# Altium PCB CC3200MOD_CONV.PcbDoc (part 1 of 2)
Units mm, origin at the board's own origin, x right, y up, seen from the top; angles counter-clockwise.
Board outline 40.99 x 49.89 mm, 2 copper layers (Top Layer, Bottom Layer), stack 1.071 mm thick; 81 components, 78 nets, 312 pads, 246 vias.
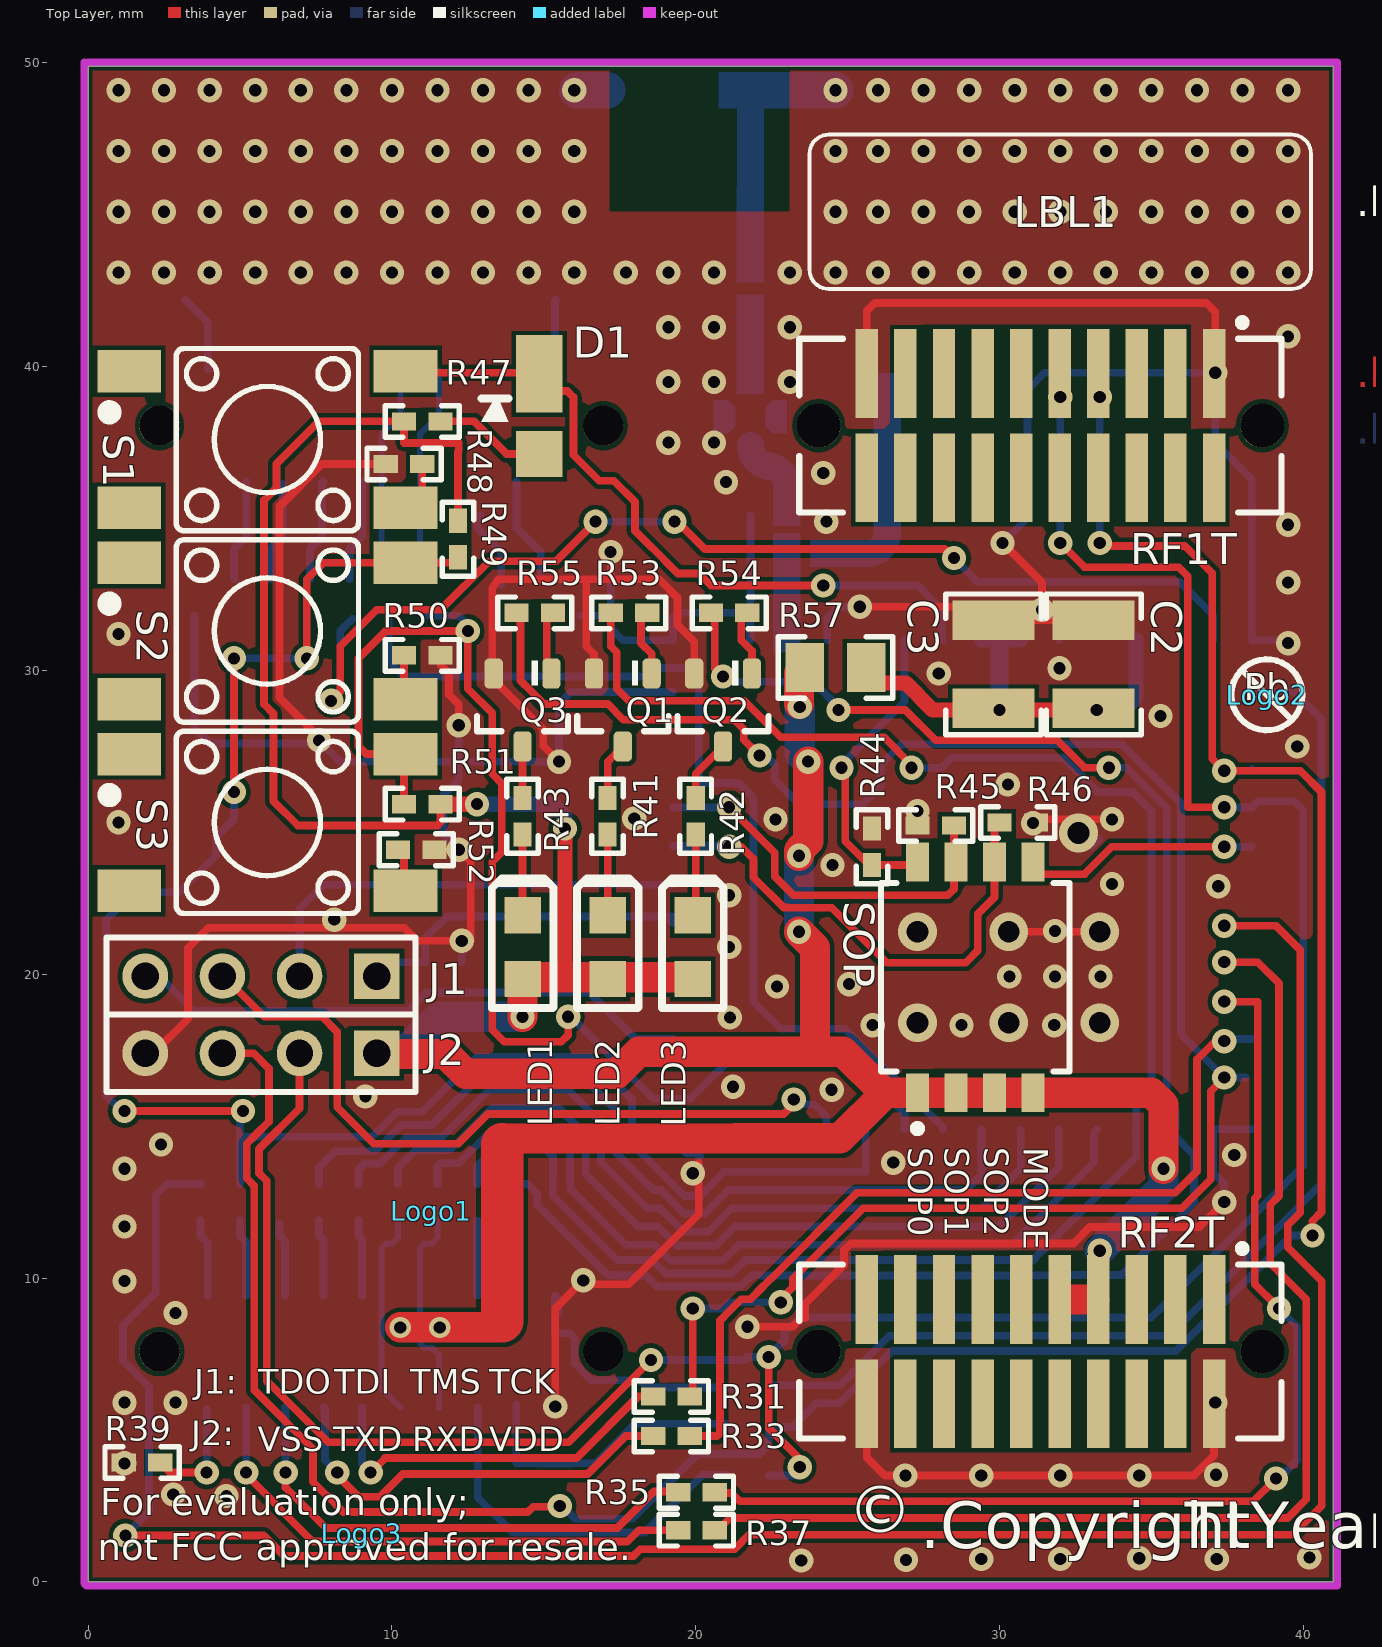
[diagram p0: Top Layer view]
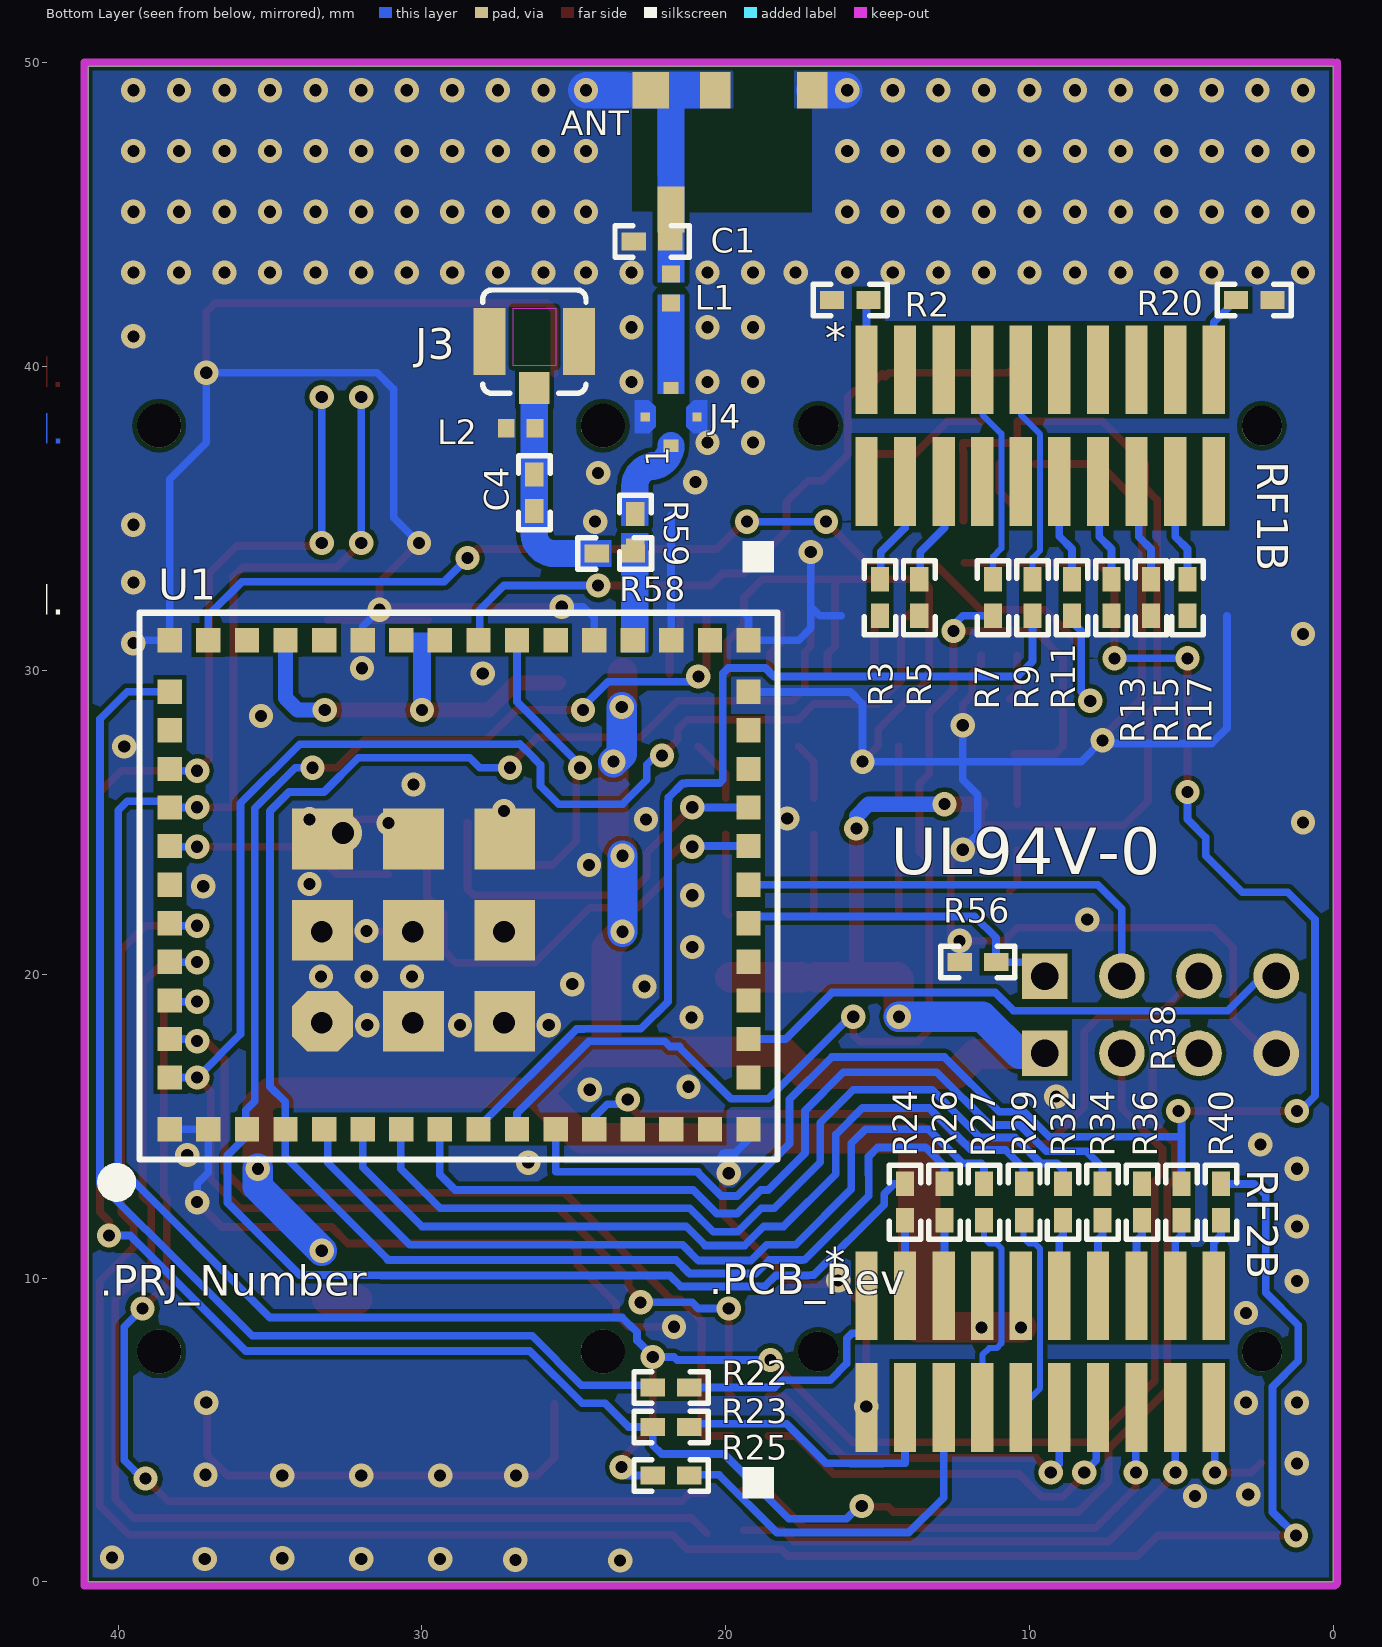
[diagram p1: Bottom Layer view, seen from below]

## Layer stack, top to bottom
Top Layer: signal copper 0.0356
Dielectric: core 1, FR-4, Dk 4.8
Bottom Layer: signal copper 0.0356

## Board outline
0,0 0,49.894 40.988,49.894 40.988,0

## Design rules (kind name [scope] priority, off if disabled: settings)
AcuteAngle [All] p1: minimum=4.50000000000000E+0001 checktracksonly=FALSE
AssemblyTestPointUsage [All] p1: valid=2
Clearance Clearance_BoardEdge_MountingHoles [OnCopper and InComponentClass('Mounting Holes') vs IsKeepOut] p1: gap=1.016
Clearance Clearance_BoardEdge_Poly [OnCopper and InPoly vs IsKeepOut] p2: gap=0.152
Clearance Clearance_BoardEdge [OnCopper and Not InComponentClass('Logo') and not InComponentClass('FiducialMark') and not InRegion(1000,500,4000,800) and Not IsKeepout vs IsKeepOut] p3: gap=0.152
Clearance Clearance_Poly [InPolygon] p4: gap=0.152
Clearance [All] p5: gap=0.152
ComponentClearance ComponentClearance_Shunt [InComponentClass('Header') vs InComponentClass('Shunt')] p1: gap=0.127 collisioncheckmode=3 verticalgap=0 showdistances=FALSE
ComponentClearance ComponentClearance_MountingHoles_FiducialMarks [InComponentClass('Mounting Holes') vs InComponentClass('FiducialMark')] p2 off: gap=0.127 collisioncheckmode=3 verticalgap=0.254 showdistances=FALSE
ComponentClearance ComponentClearance_Logo [InComponentClass('Logo')] p3: gap=1.27 collisioncheckmode=3 verticalgap=0.254 showdistances=FALSE
ComponentClearance ComponentClearance_ScrewToNut [(HasFootprint('NY PMS 440 0025 PH')) vs (HasFootprint('Keystone_1902C'))] p4: gap=0.127 collisioncheckmode=3 verticalgap=0.254 showdistances=FALSE
ComponentClearance ComponentClearance_MountingHoles [InComponentClass('Mounting Holes')] p5: gap=6.35 collisioncheckmode=3 verticalgap=2540 showdistances=FALSE
ComponentClearance ComponentClearance_SmallPassives [HasFootprint('0201*') or HasFootprint('0402*') or HasFootprint('0508') or HasFootprint('0603*') or HasFootprint('0612') or HasFootprint('0805*') or HasFootprint('0815*') or HasFootprint('0830*') or HasFootprint('1206*') or HasFootprint('1210*') or HasFootprint('1808*') or HasFootprint('1812*') or HasFootprint('1825*') or HasFootprint('2010*') or HasFootprint('2220*') or HasFootprint('2225*') or HasFootprint('2512*') or HasFootprint('2728*') or HasFootprint('3518*') vs HasFootprint('0201*') or HasFootprint('0402*') or HasFootprint('0508') or HasFootprint('0603*') or HasFootprint('0612') or HasFootprint('0805*') or HasFootprint('0815*') or HasFootprint('0830*') or HasFootprint('1206*') or HasFootprint('1210*') or HasFootprint('1808*') or HasFootprint('1812*') or HasFootprint('1825*') or HasFootprint('2010*') or HasFootprint('2220*') or HasFootprint('2225*') or HasFootprint('2512*') or HasFootprint('2728*') or HasFootprint('3518*')] p6: gap=0.508 collisioncheckmode=3 verticalgap=0.254 showdistances=FALSE
ComponentClearance ComponentClearance_THtoSMT [IsThruComponent vs IsSMTComponent] p7: gap=0.127 collisioncheckmode=3 verticalgap=0.762 showdistances=FALSE
ComponentClearance ComponentClearance_THtoTH [IsThruComponent vs IsThruComponent] p8: gap=0.127 collisioncheckmode=3 verticalgap=0.762 showdistances=FALSE
ComponentClearance [All] p9: gap=0.127 collisioncheckmode=3 verticalgap=0.254 showdistances=FALSE
DiffPairsRouting [All] p1: maxlimit=2.54 minlimit=0.254 mostfreqgap=0.254 maxuncoupledlength=25.4
FabricationTestPointUsage TestPointUsage [All] p1: valid=2 allowmultiple=FALSE
FabricationTestpoint Testpoint [All] p1: side=3 testpointundercomponent=TRUE minsize=1.016 maxsize=2.54 preferedsize=1.524 minholesize=0 maxholesize=1.016 preferedholesize=0.813 testpointgrid=0.025 allowsidetop=TRUE allowsidebottom=TRUE usegrid=TRUE gridtolerance=0
FanoutControl Fanout_LCC [IsLCC] p1: bgadir=Out bgaviamode=Centered fanoutstyle=Auto fanoutdirection=Alternating viagrid=0.025 // Fanout_LCC (Default Rule)
FanoutControl Fanout_BGA [IsBGA] p2: bgadir=Out bgaviamode=Centered fanoutstyle=Auto fanoutdirection=Alternating viagrid=0.025 // Fanout_BGA (Default Rule)
FanoutControl Fanout_Default [All] p4: bgadir=Out bgaviamode=Centered fanoutstyle=Auto fanoutdirection=Alternating viagrid=0.025 // Fanout_Default (Default Rule)
FanoutControl Fanout_Small [(CompPinCount < 5)] p5: bgadir=Out bgaviamode=Centered fanoutstyle=Auto fanoutdirection=OutThenIn viagrid=0.025 // Fanout_Small (Default Rule)
HoleSize [All] p1: absolutevalues=TRUE maxlimit=6.375 minlimit=0.203 maxpercent=80.000 minpercent=20.000
MinimumAnnularRing MinimumAnnularRing_ThermalPadVias [IsVia and InAnyComponent] p1: minimumring=0.15
MinimumAnnularRing [All] p2: minimumring=0.2
MinimumSolderMaskSliver MinimumSolderMaskSliver_Logo [InComponentClass('Logo') vs InComponentClass('Logo')] p1: minsoldermaskwidth=0.018
MinimumSolderMaskSliver [All] p2: minsoldermaskwidth=0.1
PlaneClearance [All] p1: clearance=0.152
PlaneConnect [All] p1: planeconnectstyle=Direct reliefexpansion=0.254 reliefentries=4 reliefconductorwidth=0.254 reliefairgap=0.254
PolygonConnect [All] p1: connectstyle=Direct reliefconductorwidth=0.254 reliefentries=4 polygonreliefangle="90 Angle" airgapwidth=0.254
RoutingVias ThermalPadVias [IsVia and InAnyComponent] p1: holewidth=0.2 width=0.5 viastyle="Through Hole" minholewidth=0.2 minwidth=0.5 maxholewidth=0.33 maxwidth=0.6
RoutingVias [All] p2: holewidth=0.406 width=0.864 viastyle="Through Hole" minholewidth=0.2 minwidth=0.66 maxholewidth=1.016 maxwidth=1.651
SMDToCorner [All] p1: distance=30000
SilkToSilkClearance SilkToSilkClearance_Pb-FreeLogo [(HasFootprint('Pb-Free_Overlay_Medium') OR HasFootprint('Pb-Free_Overlay_Small')) vs (HasFootprint('Pb-Free_Overlay_Medium') OR HasFootprint('Pb-Free_Overlay_Small'))] p1: silktosilkclearance=0
SilkToSilkClearance [All] p2: silktosilkclearance=0
SilkscreenOverComponentPads [IsPad] p1: minsilkscreentomaskgap=0.127
SolderMaskExpansion [All] p1: expansion=0.05
Width [All] p1: maxlimit=2.54 minlimit=0.127 preferedwidth=0.254 checkconnectedcopper=TRUE
13 further rules are at their usual default settings.

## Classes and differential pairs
component class Logo: Logo1
component class Hardware_CC3200MOD_CONV: LBL1 Logo2 Logo3 ZZ1 ZZ2 ZZ3 ZZ4
component class AssemblyNote: ZZ1 ZZ2 ZZ3 ZZ4
component class Label: LBL1
component class CC3200MOD_CONV: 0.8 ANT C1 C2 C3 C4 D1 J1 J2 J3 J4 L1 L2 LED1 LED2 LED3 Logo1 Q1 Q2 Q3 R2 R3 R5 R7 R9 R11 R13 R15 R17 R20 R22 R23 R24 R25 R26 R27 R29 R31 R32 R33 R34 R35 R36 R37 R38 R39 R40 R41 R42 R43 R44 R45 R46 R47 R48 R49 R50 R51 R52 R53 R54 R55 R56 R57 R58 R59 RF1B RF1T RF2B RF2T S1 S2 S3 SOP U1

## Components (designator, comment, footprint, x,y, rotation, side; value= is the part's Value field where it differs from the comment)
ANT "AH316M245001-T" AH316M 18.75,49.1 r180 bottom
C1 "GRM1555C1H1R0BA01D" 0402 22.425,44.125 r180 bottom
C2 "GRM32ER60J107ME20L" 1210 33.1,30.2 r90 top
C3 "GRM32ER60J107ME20L" 1210 29.8,30.2 r90 top
C4 "GRM1555C1H100JA01D" 0402 26.3,35.85 r90 bottom
D1 "D_SCHOT_DFLS160" POWERDI_123 14.85,38.7 r270 top
J1 "JTAG" HDR1X4 9.5,19.94 r180 top
J2 "Spare UART for serial flash programming" HDR1X4 9.5,17.4 r180 top
J3 "U.FL-R-SMT-1" CONN_UFL-R-SMT-1 26.3,40.825 r90 bottom
J4 "CONN_MICROWAVE-MM8030-2600" CONN_MICRO-MM8030-2600 21.8,38.35 r0 bottom
L1 "LQP15MN3N6B02D" LQP_0402 21.8,42.575 r90 bottom
L2 "DNP" LQP_0402 26.75,37.975 r180 bottom
LBL1 "Size: 0.65\" x 0.20 \"" Label_650x200 32,45.1 r0 top
LED1 "Red" 0805-LED 14.3,20.9 r90 top
LED2 "Green" 0805-LED 17.1,20.9 r90 top
LED3 "Blue" 0805-LED 19.9,20.9 r90 top
Logo1 "Texas Instruments" TI_Stacked_SolderMask_Small 11.3,12.2 r0 top
Logo2 "Pb-Free Symbol" Pb-Free_Overlay_Small 38.8,29.2 r0 top
Logo3 "FCC disclaimer" FCC_disclaimer_stacked 9,1.6 r0 top
Q1 "BSS138" SOT-23 17.6,28.7 r270 top
Q2 "BSS138" SOT-23 20.9,28.7 r270 top
Q3 "BSS138" SOT-23 14.3,28.7 r270 top
R2 "CRCW04020000Z0ED" 0402 15.9,42.2 r180 bottom
R3 "CRCW04020000Z0ED (Phantom)" 0402 14.918,32.4 r90 bottom
R5 "CRCW04020000Z0ED (Phantom)" 0402 13.627,32.4 r90 bottom
R7 "CRCW04020000Z0ED" 0402 11.2,32.4 r90 bottom
R9 "CRCW04020000Z0ED" 0402 9.9,32.4 r90 bottom
R11 "CRCW04020000Z0ED (Phantom)" 0402 8.6,32.4 r90 bottom
R13 "CRCW04020000Z0ED (Phantom)" 0402 7.3,32.4 r90 bottom
R15 "CRCW04020000Z0ED (Phantom)" 0402 6,32.4 r90 bottom
R17 "CRCW04020000Z0ED (Phantom)" 0402 4.8,32.4 r90 bottom
R20 "CRCW04020000Z0ED" 0402 2.6,42.2 r0 bottom
R22 "CRCW04020000Z0ED (Phantom)" 0402 21.8,6.4 r180 bottom
R23 "CRCW04020000Z0ED (Phantom)" 0402 21.8,5.1 r180 bottom
R24 "CRCW04020000Z0ED (Phantom)" 0402 14.1,12.5 r90 bottom
R25 "CRCW04020000Z0ED (Phantom)" 0402 21.8,3.5 r180 bottom
R26 "CRCW04020000Z0ED (Phantom)" 0402 12.8,12.5 r90 bottom
R27 "CRCW04020000Z0ED (Phantom)" 0402 11.5,12.5 r270 bottom
R29 "CRCW04020000Z0ED (Phantom)" 0402 10.175,12.5 r270 bottom
R31 "CRCW04020000Z0ED (Phantom)" 0402 19.2,6.1 r180 top
R32 "CRCW04020000Z0ED (Phantom)" 0402 8.9,12.5 r90 bottom
R33 "CRCW04020000Z0ED (Phantom)" 0402 19.2,4.8 r180 top
R34 "CRCW04020000Z0ED (Phantom)" 0402 7.6,12.5 r90 bottom
R35 "CRCW04020000Z0ED (Phantom)" 0402 20.025,2.95 r180 top
R36 "CRCW04020000Z0ED (Phantom)" 0402 6.3,12.5 r90 bottom
R37 "CRCW04020000Z0ED (Phantom)" 0402 20.025,1.7 r180 top
R38 "CRCW04020000Z0ED (Phantom)" 0402 5,12.5 r90 bottom
R39 "CRCW04020000Z0ED" 0402 1.775,3.925 r0 top
R40 "CRCW04020000Z0ED (Phantom)" 0402 3.7,12.5 r90 bottom
R41 "CRCW0402390RJNED" 0402 17.1,25.2 r270 top
R42 "CRCW0402390RJNED" 0402 20,25.2 r270 top
R43 "CRCW0402390RJNED" 0402 14.3,25.2 r270 top
R44 "CRCW0402100KJNED" 0402 25.8,24.2 r270 top
R45 "CRCW0402100KJNED" 0402 27.9,24.9 r0 top
R46 "CRCW04022K70JNED" 0402 30.6,25 r180 top
R47 "CRCW0402100KJNED" 0402 11,38.2 r0 top
R48 "CRCW0402100RJNED" 0402 10.4,36.8 r180 top
R49 "CRCW04021K00JNED" 0402 12.175,34.325 r270 top
R50 "CRCW040210K0JNED" 0402 11,30.5 r0 top
R51 "CRCW04021K00JNED" 0402 11,25.6 r180 top
R52 "CRCW040210K0JNED" 0402 10.8,24.1 r0 top
R53 "CRCW040210K0JNED" 0402 17.8,31.9 r0 top
R54 "CRCW040210K0JNED" 0402 21.1,31.9 r0 top
R55 "CRCW040210K0JNED" 0402 14.7,31.9 r0 top
R56 "CRCW0402100KJNED" 0402 11.7,20.4 r180 bottom
R57 "CRCW08050000Z0EA" 0805_HV 24.6,30.1 r0 top
R58 "CRCW04020000Z0ED (Phantom)" 0402 23.65,33.85 r180 bottom
R59 "CRCW04020000Z0ED" 0402 22.975,34.55 r90 bottom
RF1B "HEADER_SFM-110-02-SM-D-A-K-TR" HEADER_TFM-110-02-SM 9.652,38.06 r180 bottom locked
RF1T "TFM-110-02-S-D-A-K-TR" Samtec_TFM-110-02-S-D-A-K 31.348,38.06 r180 top locked
RF2B "HEADER_SFM-110-02-SM-D-A-K-TR" HEADER_TFM-110-02-SM 9.652,7.58 r180 bottom locked
RF2T "TFM-110-02-S-D-A-K-TR" Samtec_TFM-110-02-S-D-A-K 31.348,7.58 r180 top locked
S1 "4-1437565-1" SW_FSM4JSMA 5.9,37.6 r90 top
S2 "4-1437565-1" SW_FSM4JSMA 5.9,31.3 r90 top
S3 "4-1437565-1" SW_FSM4JSMA 5.9,25 r90 top
SOP "1571983-5" SW_1571983-5 29.2,19.9 r90 top
U1 "CC3200MOD" CC3200MOD 38.3,14.9 r180 bottom locked
ZZ1 "This Assembly Note is for PCB labels only" AssemblyNoteLabel -0.1,56.075 r0 top
ZZ2 "These assemblies are ESD sensitive, ESD precautions shall be observed." AssemblyNote -0.125,54.275 r0 top
ZZ3 "These assemblies must be clean and free from flux and all contaminants. Use of no clean flux is not acceptable." AssemblyNote -0.125,52.55 r0 top
ZZ4 "These assemblies must comply with workmanship standards IPC-A-610 Class 2, unless otherwise specified." AssemblyNote -0.175,57.825 r0 top

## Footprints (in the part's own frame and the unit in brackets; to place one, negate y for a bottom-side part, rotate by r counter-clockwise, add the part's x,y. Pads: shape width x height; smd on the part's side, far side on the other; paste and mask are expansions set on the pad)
0402 [mm] "0402 from SM-752 data"
  rect 0.8x0.6 smd: 1(-0.6,0) 2(0.6,0)
  silkscreen extent -1.22,-0.52 1.22,0.52, body extent -0.55,-0.3 0.55,0.3, height 0.6
0805-LED [mm]
  rect 1.2x1.2 smd: 1(-1.055,-0.005) 2(1.045,-0.005)
  silkscreen extent -2.01,-1.02 2.26,1.01
0805_HV [mil] "0805 with 30mil clearance between pads"
  rect 50x63 smd: 1(-40,0) 2(40,0)
  silkscreen extent -74,-40 74,40, body extent -43,-29 43,29, height 43
1210 [mm] "1210 from SM-752 data"
  rect 1.3x2.7 smd: 1(-1.45,0) 2(1.45,0)
  silkscreen extent -2.32,-1.57 2.32,1.57, body extent -1.7,-1.35 1.7,1.35, height 1.35
AH316M [mm]
  rect 1.2x1.2 smd paste+0 mask+0: 1(-3.725,0)
  rect 1x1.2 smd: 1(-1.6,0) 2(1.6,0)
  rect 0.889x1.524 smd paste+0 mask+0: 3(-3.056,-3.925)
  Top Layer region: -4.35,0.6 -2,0.6 -2,-0.6 -4.35,-0.6
  Top Layer region: -3.5,-0.3 -2.611,-0.3 -2.611,-4.5 -3.5,-4.5
  Top Layer pour cut-out: -4.35,-0.6 -3.5,-0.6 -3.501,-4 -4.35,-4
  Top Layer pour cut-out: -1,0.6 1,0.6 1,-0.6 -1,-0.6
  Top Layer pour cut-out: -2.625,-0.6 1.6,-0.6 1.6,-4 1.575,-4.025 -2.625,-4.025
  Bottom Layer pour cut-out: 1.6,0.6 1.6,-4 -4.35,-4 -4.35,0.6
AssemblyNote [mm] "Assembly Note"
AssemblyNoteLabel [mm] "Assembly Note for PCB Labels"
CC3200MOD [mm]
  rect 0.8x0.8 smd: 1(0,0) 2(1.27,0) 3(2.54,0) 4(3.81,0) 5(5.08,0) 6(6.35,0) 7(7.62,0) 8(8.89,0) 9(10.16,0) 10(11.43,0) 11(12.7,0) 12(13.97,0) 13(15.24,0) 14(16.51,0) 15(17.78,0) 16(19.05,0) 17(19.05,1.7) 18(19.05,2.97) 19(19.05,4.24) 20(19.05,5.51) 21(19.05,6.78) 22(19.05,8.05) 23(19.05,9.32) 24(19.05,10.59) 25(19.05,11.86) 26(19.05,13.13) 27(19.05,14.4) 28(19.05,16.1) 29(17.78,16.1) 30(16.51,16.1) 31(15.24,16.1) 32(13.97,16.1) 33(12.7,16.1) 34(11.43,16.1) 35(10.16,16.1) 36(8.89,16.1) 37(7.62,16.1) 38(6.35,16.1) 39(5.08,16.1) 40(3.81,16.1) 41(2.54,16.1) 42(1.27,16.1) 43(0,16.1) 44(0,14.4) 45(0,13.13) 46(0,11.86) 47(0,10.59) 48(0,9.32) 49(0,8.05) 50(0,6.78) 51(0,5.51) 52(0,4.24) 53(0,2.97) 54(0,1.7)
  oct 2x2 smd: 55(5.025,3.55)
  rect 2x2 smd: 56(8.025,3.55) 57(11.025,3.55) 58(5.025,6.55) 59(8.025,6.55) 60(11.025,6.55) 61(5.025,9.55) 62(8.025,9.55) 63(11.025,9.55)
  silkscreen extent -2.07,-2.07 20,17
CONN_MICRO-MM8030-2600 [mm]
  rect 0.5x0.4 smd: 1(0,0.95) 2(0,-0.95)
  rect 0.3x0.3 smd: 3(-0.85,0) 4(0.85,0)
  Top Layer region: -1.199,0.544 -1.199,-0.55 -0.74,-0.552 -0.498,-0.32 -0.5,0.322 -0.737,0.546
  Top Layer region: 1.198,-0.546 1.198,0.548 0.739,0.55 0.497,0.319 0.499,-0.324 0.735,-0.548
CONN_UFL-R-SMT-1 [mm] "Hirose recommended land pattern http://www.hirose.co.jp/cataloge_hp/e32119372.pdf 2009.2"
  rect 1.05x1 smd: 1(-1.525,0)
  rect 2.2x1.05 smd: 2(0,1.475) 3(0,-1.475)
  Top Layer keep-out region: -0.8,0.701 1.1,0.701 1.1,-0.699 -0.8,-0.699
  silkscreen extent -1.7,-1.7 1.7,1.7, body extent -1.55,-1.5 1.55,1.5, height 1.27
FCC_disclaimer_stacked [mm]
HDR1X4 [mm] "Connector; Header; 4 Position"
  rect 1.5x1.5 hole 0.9: 1(0,0)
  round 1.5 hole 0.9: 2(2.54,0) 3(5.08,0) 4(7.62,0)
  silkscreen extent -1.27,-1.27 8.89,1.27
HEADER_TFM-110-02-SM [mil]
  rect 29x115 smd: 1(-225,-72.5) 2(-225,72.5) 3(-175,-72.5) 4(-175,72.5) 5(-125,-72.5) 6(-125,72.5) 7(-75,-72.5) 8(-75,72.5) 9(-25,-72.5) 10(-25,72.5) 11(25,-72.5) 12(25,72.5) 13(75,-72.5) 14(75,72.5) 15(125,-72.5) 16(125,72.5) 17(175,-72.5) 18(175,72.5) 19(225,-72.5) 20(225,72.5)
  round 52 hole 52 unplated: 21(287.5,0) 22(-287.5,0)
  silkscreen extent -385,-190 -345,-150
Label_650x200 [mm] "Thermal Transfer Label"
  silkscreen extent -8.25,-2.54 8.26,2.54, body extent -8.27,-2.55 8.27,2.55, height 0.03
LQP_0402 [mm] "SMD, 2-Leads, Body 1.1x0.6mm"
  rect 0.55x0.6 smd: 1(-0.475,0) 2(0.475,0)
  body extent -0.55,-0.3 0.55,0.3, height 0.45
Pb-Free_Overlay_Small [mm]
  silkscreen extent -1.16,-1.17 1.17,1.17
POWERDI_123 [mil]
  rect 100x60 smd: 1(-42,0)
  rect 60x60 smd: 2(62,0)
  silkscreen extent -15,-75 20,-40
Samtec_TFM-110-02-S-D-A-K [mm] "Samtec"
  rect 0.74x2.92 smd paste+0: 1(-5.715,-1.715) 2(-5.715,1.715) 3(-4.445,-1.715) 4(-4.445,1.715) 5(-3.175,-1.715) 6(-3.175,1.715) 7(-1.905,-1.715) 8(-1.905,1.715) 9(-0.635,-1.715) 10(-0.635,1.715) 11(0.635,-1.715) 12(0.635,1.715) 13(1.905,-1.715) 14(1.905,1.715) 15(3.175,-1.715) 16(3.175,1.715) 17(4.445,-1.715) 18(4.445,1.715) 19(5.715,-1.715) 20(5.715,1.715)
  round 1.45 hole 1.45 unplated paste+0: ""(-7.305,0) ""(7.305,0)
  silkscreen extent -7.94,-3.51 7.94,2.86, body extent -7.95,-2.98 7.93,2.99, height 5.85
SOT-23 [mm] "SOT23, 3-Leads, Body 2.9x1.3mm, Pitch 0.95mm, Lead Span 2.5mm, IPC Medium Density"
  rrect50% 1x0.6 smd: 1(-1.2,0.95) 2(-1.2,-0.95) 3(1.2,0)
  silkscreen extent -1.63,-1.5 0.7,1.5, body extent -1.16,-1.45 1.21,1.45, height 1
SW_1571983-5 [mm] "SMD, 8-Leads, Pitch 1.27mm"
  rect 1.27x0.76 smd: 1(-3.795,1.905) 2(-3.795,0.635) 3(-3.795,-0.635) 4(-3.795,-1.905) 5(3.795,-1.905) 6(3.795,-0.635) 7(3.795,0.635) 8(3.795,1.905)
  silkscreen extent -5.1,-3.1 3.1,3.1, body extent -4.06,-3.1 4.06,3.1, height 2.31
SW_FSM4JSMA [mm] "Alcoswitch"
  rect 1.4x2.1 smd: 1(2.25,4.55) 2(2.25,-4.55) 3(-2.25,4.55) 4(-2.25,-4.55)
  silkscreen extent -3,-3 3,5.4, body extent -3,-5 3,5, height 5.1
TI_Stacked_SolderMask_Small [mm]
  rect 0x0 smd paste-3.175 mask-3.175: 0(0,0)

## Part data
C1: "CAP, CERM, 1 pF, 50 V, +/- 10%, C0G/NP0, 0402"
C2 C3: "CAP, CERM, 100 µF, 6.3 V, +/- 20%, X5R, 1210"
C4: "CAP, CERM, 10 pF, 50 V, +/- 5%, C0G/NP0, 0402"
D1: "Diode, Schottky, 1A, 60V"
J1 J2: library part "Header 4", "Header, 4-Pin"
J3: "Connector, Ultra-Mini Coaxial, SMD"
J4: "Connector, Micrwave, 50 Ohm Coax"
L1 L2: library part LQP15MN10NG02D, "Inductor, Film,  3.6 nH, 0.1 A, 1.3 ohm, SMD"
LBL1: library part THT-14-423-10, "Thermal Transfer Printable Labels, 0.650\" W x 0.200\" H - 10,000 per roll"
LED1 LED2 LED3: library part LED-0805
Logo1: library part TI_Logo, "Texas Instrument Corporate Signature"
Logo2: library part Pb-Free
Logo3: library part FCC_disclaimer, "FCC_disclaimer"
Q1 Q2 Q3: "MOSFET, N-CH, 50 V, 0.22 A, SOT-23"
R2 R7 R9 R20 R39 R59: "RES, 0, 5%, 0.063 W, 0402"
R3 R5 R11 R13 R15 R17 R22 R23 R24 R25 R26 R27 R29 R31 R32 R33 R34 R35 R36 R37 R38 R40 R58: library part CRCW04020000Z0ED, "RES, DNP, 5%, 0.063 W, 0402"
R41 R42 R43: "RES, 390, 5%, 0.063 W, 0402"
R44 R45 R47 R56: "RES, 100 k, 5%, 0.063 W, 0402"
R46: "RES, 2.7 k, 5%, 0.063 W, 0402"
R48: "RES, 100, 5%, 0.063 W, 0402"
R49 R51: "RES, 1.0 k, 5%, 0.063 W, 0402"
R50 R52 R53 R54 R55: "RES, 10 k, 5%, 0.063 W, 0402"
R57: "RES, 0, 5%, 0.125 W, 0805"
RF1B RF2B: library part HEADER_TFM-110-02-SM-D-A-K-TR, "Header, SMT 10X2 pin, Shrouded"
RF1T RF2T: "CONN SHRD HDR HDR 20 POS 1.27MM SLDR ST SMD"
S1 S2 S3: "Switch, Tactile, SPST-NO, 0.05A, 12V, SMT"
SOP: "Switch, SPST, 4 Pos, Top Actuated, SMD"
ZZ1: library part AssemblyNoteLabel
ZZ2 ZZ3 ZZ4: library part AssemblyNote

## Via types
v1: diameter 0.8, hole 0.4, Top Layer to Bottom Layer, tented both sides, 237 vias
v2: diameter 1.27, hole 0.711, Top Layer to Bottom Layer, tented bottom, 7 vias
v3: diameter 0.7, hole 0.4, Top Layer to Bottom Layer, tented both sides, 2 vias

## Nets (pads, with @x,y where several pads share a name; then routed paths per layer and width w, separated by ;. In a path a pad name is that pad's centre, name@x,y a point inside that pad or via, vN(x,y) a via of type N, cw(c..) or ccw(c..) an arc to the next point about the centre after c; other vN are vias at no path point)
DGND: ANT.1 ANT.2 C1.1 C2.2 C3.2 J2.4 J3.2 J3.3 J4.3 J4.4 L2.1 Q1.2 Q2.2 Q3.2 R2.1 R20.1 R39.1 R44.1 R45.1 R46.1 R48.2 R50.2 R52.2 R56.1 RF1T.1 RF1T.19 RF2B.1 RF2T.2 RF2T.20 U1.1 U1.2 U1.16 U1.27 U1.28 U1.30 U1.32 U1.38 U1.43 U1.55 U1.56 U1.57 U1.58 U1.59 U1.60 U1.61 U1.62 U1.63 | length 205.1
  Top Layer w0.254: J2.4@1.88,17.4 2.15,17.4 3.289,18.539 3.289,20.868 3.952,21.531 10.408,21.531 10.839,21.1 v1(12.3,21.1) 12.592,21.1 12.592,23.708 v1(12.2,24.1) R52.2@11.6,24.1 ; v1(7.6,27.7) 7.6,27.8 6.3,29.1 6.3,35.4 7.7,36.8 R48.2@9.8,36.8 ; R50.2@11.6,30.5 11.6,30.189 11.881,29.908 11.881,29.201 12.2,28.882 v1@12.2,28.3 ; v1(15.375,5.775) 15.375,9 v1(16.3,9.925) ; v1(15.5,27) 14.981,27.519 14.981,28.07 13.35,29.701 Q3.2@13.35,29.9 13.3,29.95 13.3,32.7 13.5,33 16.4,33 ; v1@16.65,9.8 17.8,9.8 20.1,12.1 20.1,13.8 ; Q1.2@16.65,29.9 16.65,30.55 16.4,30.8 16.4,33 ; v1(17.2,33.9) 17.2,33 ; Q2.2@19.95,29.9 19.95,30.95 19.4,31.5 19.4,32.4 18.8,33 17.2,33 ; v1@21.587,8.4 23.2,8.4 23.486,8.686 23.6,8.686 23.6,9.15 24.882,10.433 24.882,10.913 25.105,11.136 26.161,11.136 32.431,11.136 32.977,11.681 36.581,11.681 v1(37.4,12.5) ; v1(25.4,32.1) 31.3,32.1 v1(31.4,32) 31.4,32.9 v1(30.1,34.2) ; RF2T.20@25.633,5.865 25.633,4.092 26.225,3.5 36.4,3.5 37.063,4.163 RF2T.2@37.063,5.865 ; RF1T.19@25.633,39.775 25.633,41.833 25.9,42.1 36.8,42.1 37.1,41.8 v1(37.1,39.8) ; C3.2@29.8,31.65 C2.2@33.1,31.65 ; v2(30.3,21.4) v2(33.3,21.4) ; R46.1@31,25 31.1,25.1 v1(33.7,25.1) ; 16.4,33 17.2,33
  Bottom Layer w0.254: 3.5,31.8 3.5,28.1 4,27.6 7.5,27.6 v1(7.6,27.7) 8.3,27 12.2,27 ; v1(12.2,24.1) 11.7,24.6 11.7,25.9 12.2,26.4 12.2,27 ; v1(12.2,28.2) 12.2,27 ; R56.1@12.3,20.4 v1(12.3,21.1) ; v1(16,49.1) v1@16.1,49.2 ; 16.2,31.8 16.9,31.8 17.2,32.1 ; ANT.2@17.181,49.2 ANT.2@17.281,49.1 ; v1(17.2,33.9) 17.2,32.1 ; U1.16@19.25,14.9 19.25,14.55 19.681,14.119 20.031,14.119 ; U1.27@19.25,29.3 19.242,29.292 15.892,29.292 15.5,28.9 v1(15.5,27) 12.2,27 ; 19.962,14.119 20.031,14.119 ; v1@20.101,13.676 20.101,13.551 20.1,13.55 20.1,13.8 20.1,14.05 ; 20.141,14.009 20.1,14.05 ; U1.30@21.8,31.01 U1.30@21.79,31 21.79,31.81 ; 21.8,35.1 21.8,31.82 21.79,31.81 ; U1.32@24.33,31 24.33,31.73 24.7,32.1 v1(25.4,32.1) ; v1(30.1,34.2) 30.925,35.025 30.925,39.275 30.938,39.263 31.475,39.8 v1(37.1,39.8) 37.1,37.5 38.3,36.3 U1.43@38.3,31 v1@39.4,31 ; v1(31.4,32) 31.95,31.45 U1.38@31.95,31 ; U1.61@33.025,24.2 U1.61@33.275,24.45 ; v1(37.4,12.5) 37.4,13.1 37.03,13.47 U1.2@37.03,14.9 U1.1@38.3,14.9 ; 17.2,32.1 17.2,31.4 17.6,31 U1.28@19.25,31 19.25,31.75 19.4,31.9 21.7,31.9 21.79,31.81 ; 20.031,14.119 20.05,14.1 ; 20.05,14.1 20.1,14.05 ; 20.05,14.1 20.1,14.1 20.1,14.05
  Bottom Layer w1.2: v1@16.1,49.1 ANT.2@17.081,49.1 ; 23.325,49.1 v1(24.6,49.1)
  other v1: 23.475,0.7 26.925,0.725 29.4,0.75 32,0.75 37.15,0.75 34.6,0.775 40.2,0.8 4.55,2.825 2.8,2.875 26.9,3.5 29.4,3.5 32,3.5 34.6,3.5 37.125,3.525 1.2,3.9 1.2,5.9 2.875,5.9 37.1,5.9 21.7,8.4 2.875,8.85 1.2,9.9 1.2,11.7 19.9,13.45 1.2,13.6 26.5,13.8 37.725,14.05 2.4,14.4 9.125,15.975 24.475,16.2 21.225,16.3 25.825,18.325 28.75,18.325 31.8,18.325 21.125,18.575 22.675,19.6 25.05,19.675 30.325,19.925 31.825,19.925 33.325,19.925 21.1,20.9 31.825,21.425 8.1,21.8 21.1,22.6 37.2,22.9 33.7,22.975 24.5,23.6 31.1,24.975 1,25 22.625,25.1 17.975,25.125 27.3,25.375 30.275,26.25 39.8,27.5 35.3,28.5 28,29.9 31.975,30.075 39.5,30.9 1,31.2 39.5,32.9 39.5,34.8 24.3,34.9 21,36.2 24.2,36.5 19.1,37.5 20.6,37.5 19.1,39.5 20.6,39.5 23.1,39.5 39.5,41 19.1,41.3 20.6,41.3 23.1,41.3 1,43.1 2.5,43.1 4,43.1 5.5,43.1 7,43.1 8.5,43.1 10,43.1 11.5,43.1 13,43.1 14.5,43.1 16,43.1 17.7,43.1 19.1,43.1 20.6,43.1 23.1,43.1 24.6,43.1 26,43.1 27.5,43.1 29,43.1 30.5,43.1 32,43.1 33.5,43.1 35,43.1 36.5,43.1 38,43.1 39.5,43.1 1,45.1 2.5,45.1 4,45.1 5.5,45.1 7,45.1 8.5,45.1 10,45.1 11.5,45.1 13,45.1 14.5,45.1 16,45.1 24.6,45.1 26,45.1 27.5,45.1 29,45.1 30.5,45.1 32,45.1 33.5,45.1 35,45.1 36.5,45.101 38,45.1 39.5,45.1 1,47.1 2.5,47.1 4,47.1 5.5,47.1 7,47.1 8.5,47.1 10,47.1 11.5,47.1 13,47.1 14.5,47.1 16,47.1 24.6,47.1 26,47.1 27.5,47.1 29,47.1 30.5,47.1 32,47.1 33.5,47.1 35,47.1 36.5,47.1 38,47.1 39.5,47.1 1,49.1 2.5,49.1 4,49.1 5.5,49.1 7,49.1 8.5,49.1 10,49.1 11.5,49.1 13,49.1 14.5,49.1 26,49.1 27.5,49.1 29,49.1 30.5,49.1 32,49.1 33.5,49.1 35,49.1 36.5,49.1 38,49.1 39.5,49.1
  other v2: 27.3,18.4 30.3,18.4 33.3,18.4 27.3,21.4 32.6,24.65
GPIO0: R22.1 U1.44 | length 38.9
  Bottom Layer w0.254: R22.1@22.4,6.4 22.475,6.475 24.75,6.475 26.375,8.1 35.575,8.1 ; 35.603,8.122 39.09,11.608 39.108,11.608 40.6,13.1 40.6,28.4 39.7,29.3 U1.44@38.3,29.3
GPIO1: J2.3 R23.1 RF1T.7 U1.46 | length 89.2
  Top Layer w0.254: J2.3@4.42,17.4 5.45,17.4 5.95,16.9 5.95,15.15 ; 5.937,15.138 5.95,15.15 ; 7.876,2.824 7.4,3.3 7.4,4.382 5.525,6.257 5.518,6.257 5.469,6.306 5.469,13.031 5.219,13.281 5.219,14.418 5.525,14.725 5.95,15.15 ; 7.881,2.819 8.4,2.3 14.475,2.3 14.65,2.475 15.675,2.475 v1@15.7,2.5 ; v1(33.3,34.2) 33.4,34.1 36.1,34.1 37,33.2 37,27.1 v1(37.4,26.7) 39.9,26.7 40.6,26 40.6,12.175 40.3,11.875 40.3,11.3 v1@40.2,11.2
  Bottom Layer w0.254: v1@15.6,2.5 16.025,2.075 17.925,2.075 20.058,4.208 22.108,4.208 22.4,4.5 R23.1@22.4,5.1 23.2,5.1 23.975,5.875 24.725,5.875 26.45,7.6 35.8,7.6 39.6,11.4 v1@40,11.4 ; v1@33.3,34.4 v1(33.3,39) ; v1(37.4,26.7) 38.24,26.7 U1.46@38.3,26.76 ; v1@40.2,11.2 v1@40.4,11.4
  other v1: 15.525,2.5 40.3,11.4
GPIO2: J2.2 R25.1 RF1T.9 U1.47 | length 89.7
  Top Layer w0.254: J2.2@6.96,17.4 6.96,15.585 5.625,14.25 5.625,13.45 5.875,13.2 5.875,6.6 5.906,6.569 5.931,6.569 7.9,4.6 15.825,4.6 18.4,7.175 v1@18.4,7.4 ; v1(22.4,7.4) 22.4,5.064 23.664,3.8 23.7,3.8 23.55,3.8 23.575,3.825 23.575,3.925 v1@23.426,3.776 ; v1(32,34.2) 32.8,33.4 35.9,33.4 36.2,33.1 36.2,25.5 v1(37.4,25.5)
  Bottom Layer w0.254: v1@18.4,7.4 18.5,7.3 21.6,7.3 21.7,7.4 v1(22.4,7.4) 22.4,7.425 22.919,7.944 22.919,8.219 23.119,8.419 23.123,8.419 23.404,8.7 35,8.7 40,13.7 40,25.4 39.7,25.7 38.51,25.7 U1.47@38.3,25.49 v1@37.4,25.49 ; R25.1@22.4,3.5 23.3,3.5 23.6,3.8 23.7,3.8 23.55,3.8 23.575,3.825 23.575,3.925 v1@23.426,3.776 ; v1@32,34.4 v1(32,39)
  other v1: 23.426,3.775 18.525,7.3
GPIO3: SOP.5 U1.48 | length 7.6
  Top Layer w0.254: SOP.5@31.1,23.295 32.795,23.295 33.7,24.2 v1(37.4,24.2)
  Bottom Layer w0.254: v1(37.4,24.2) 38.28,24.2 U1.48@38.3,24.22
GPIO4: U1.49
GPIO5: R40.2 U1.50 | length 76.9
  Top Layer w0.254: v1(1.225,1.525) 5.775,1.525 6.45,0.85 17.95,0.85 18.175,1.075 21.275,1.075 21.75,1.55 39.65,1.55 40.607,2.507 40.607,9.893 39.487,11.013 39.487,11.737 ; v1(37.4,21.6) 39.1,21.6 39.9,20.8 39.9,12.149 39.5,11.749
  Bottom Layer w0.254: v1(1.225,1.525) 2,2.3 2,6.425 1.15,7.275 1.15,8.45 2.225,9.525 2.225,12.725 2.6,13.1 R40.2@3.7,13.1 ; v1(37.4,21.6) U1.50@38.22,21.6
GPIO6: R37.1 U1.51 | length 40.6
  Top Layer w0.254: R37.1@20.625,1.6 21.125,2.1 39.482,2.1 40.099,2.717 40.099,9.301 38.908,10.492 38.908,12.408 39.2,12.7 39.2,19.7 38.5,20.4 37.5,20.4 v1@37.4,20.3
  Bottom Layer w0.254: v1(37.4,20.4) U1.51@38.221,20.4 ; U1.51@38.231,20.41 U1.51@38.3,20.41
GPIO7: R35.1 U1.52 | length 40
  Top Layer w0.254: R35.1@20.675,2.925 21.175,2.925 21.45,2.65 38.35,2.65 v1(39.1,3.4) ; v1(37.4,19.1) 38.5,19.1 38.5,12.718 38.4,12.618 38.4,9.8 v1@39.1,9.1 ; v1@39.1,9 v1@39.15,8.95 ; v1@39.1,9 v1@39.15,8.95 ; v1@39.1,9 v1@39.2,8.9 ; v1@39.15,8.95 v1@39.2,8.9 ; v1@39.15,8.95 v1@39.2,8.9
  Bottom Layer w0.254: v1(37.4,19.1) U1.52@38.26,19.1 ; v1(39.1,3.4) v1@39.1,3.3 ; v1(39.2,9) 39.8,8.4 39.8,4 ; v1@39.1,3.3 v1@39.15,3.35 ; v1@39.1,3.3 v1@39.15,3.35 ; v1@39.1,3.3 39.8,4 ; v1@39.1,3.3 v1@39.15,3.35 ; v1@39.15,3.35 39.8,4 ; v1@39.15,3.35 39.8,4
GPIO8: R33.1 U1.53 | length 28.2
  Top Layer w0.254: R33.1@19.8,4.8 20.7,4.8 20.8,4.9 20.8,8.6 20.919,8.719 20.919,8.723 21.496,9.3 21.8,9.3 22.019,9.519 22.019,9.523 22.476,9.981 22.481,9.981 25.308,12.808 35.79,12.808 36.5,13.518 36.5,17.2 ; 36.508,17.208 37.1,17.8 v1(37.4,17.8)
  Bottom Layer w0.254: v1(37.4,17.8) 37.47,17.87 U1.53@38.3,17.87
GPIO9: R31.1 R55.1 U1.54 | length 65.8
  Top Layer w0.254: R55.1@14.231,31.769 14.231,29.669 14.569,29.331 14.999,28.9 17.1,28.9 17.619,28.381 21.27,28.381 21.581,28.07 21.581,27.719 22,27.3 v1@22,27 ; R31.1@19.8,6.1 19.9,6.2 19.9,8.4 v1(19.9,9) ; v1@22.7,9 23,9 22.75,9.25 23.2,9.7 23.2,9.982 25.518,12.3 36,12.3 36.298,12.598 36.95,13.25 36.95,16.15 v1@37.35,16.55 ; R55.1@13.9,31.9 R55.1@14,31.8 ; R55.1@13.9,31.9 R55.1@14,31.8 ; R55.1@13.9,31.9 R55.1@14.031,31.769 ; R55.1@14,31.8 R55.1@14.031,31.769 ; R55.1@14,31.8 R55.1@14.031,31.769
  Bottom Layer w0.254: v1@19.9,9.2 20.1,9 20.9,9 21.1,9.2 22.65,9.2 v1@22.75,9.3 ; v1(22.1,27.2) 22.3,27.2 22.6,26.9 22.6,26.4 23.4,25.6 25.5,25.6 26.1,26.2 26.1,26.9 26.319,27.119 26.319,27.123 26.777,27.581 26.781,27.581 26.787,27.575 34.025,27.575 35.975,25.625 35.975,18.025 v1(37.4,16.6) U1.54@38.1,16.6 ; v1@22.7,9 22.982,9 22.991,9.009 v1(22.8,9.2)
GPIO10: R24.2 R54.1 U1.3 | length 56.9
  Top Layer w0.254: R54.1@20.5,31.9 20.631,31.769 20.631,30.069 v1@20.8,29.9 ; v1@25.1,28.7 26.9,28.7 27.9,27.7 31.9,27.7 32.8,26.8 v1(33.6,26.8) 33.6,26.9 v1@33.65,26.95
  Bottom Layer w0.254: R24.2@14.1,13.1 14.46,13.1 14.781,12.779 14.781,12.419 17.1,10.1 17.182,10.1 17.19,10.092 17.271,10.092 17.279,10.084 18.356,10.084 18.715,9.725 21.485,9.725 21.844,10.084 31.339,10.084 31.347,10.092 31.91,10.092 31.918,10.1 34.025,10.1 36.4,12.475 36.4,14.04 35.76,14.68 U1.3@35.76,14.874 ; v1(20.9,29.8) 21.075,29.625 23.875,29.625 v1@24.8,28.7 ; v1(33.6,26.8) 34.175,26.8 35.508,25.467 35.508,15.817 35.8,15.525 35.8,14.94 U1.3@35.76,14.9 U1.3@35.76,14.874 ; U1.3@35.66,14.874 35.752,14.874 U1.3@35.76,14.874
  other v1: 24.7,28.7
GPIO11: R26.2 R53.1 U1.4 | length 60.4
  Top Layer w0.254: R53.1@17,31.9 R53.1@17.1,31.8 ; R53.1@17.2,31.8 17.2,30.8 17.4,30.6 17.4,29.4 17.8,29 21.6,29 22.8,27.8 26.2,27.8 27.1,26.9 v1(27.1,26.8)
  Bottom Layer w0.254: R26.2@12.8,13.1 12.8,13.675 13.425,14.3 15,14.3 15.3,14 15.291,12.709 17.4,10.6 17.482,10.6 17.49,10.592 18.566,10.592 19.008,10.15 21.192,10.15 21.634,10.592 31.129,10.592 31.137,10.6 31.137,10.637 34.5,14 34.5,14.82 34.49,14.83 U1.4@34.49,14.9 34.5,14.91 34.5,15.8 35,16.3 35,25.375 34.375,26 33.225,26 32.1,27.125 28.425,27.125 28.1,26.8 v1(27.1,26.8)
GPIO12: R9.1 U1.9 | length 32.4
  Bottom Layer w0.254: R9.1@9.9,31.8 9.9,30.3 10.4,29.8 18.411,29.8 18.692,30.081 19.919,30.081 20.1,29.9 20.1,26.4 20.2,26.3 21.3,26.3 21.319,26.281 21.423,26.281 21.881,25.824 21.881,25.719 21.9,25.7 21.9,19.1 22.794,18.206 24.668,18.206 24.675,18.2 24.909,18.2 28.14,14.969 U1.9@28.14,14.9
GPIO13: R7.1 R51.2 S3.2 U1.10 | length 43.5
  Top Layer w0.254: R51.2@10.4,25.6 S3.2@10.4,27.15 ; v1(15.8,18.6) 15.8,18 15.575,17.775 13.7,17.775 13.3,18.175 13.3,23.7 13.619,24.019 13.619,26.281 13.3,26.6 13.3,28.6 12.5,29.4 v1(12.5,31.3) 9.8,31.3 8.9,30.4 8.9,27.5 9.15,27.25 S3.2@10.45,27.25 S3.2@10.5,27.25 ; S3.2@10.4,27.15 S3.2@10.475,27.225 ; S3.2@10.4,27.15 S3.2@10.475,27.225 ; S3.2@10.4,27.15 S3.2@10.5,27.25 ; S3.2@10.4,27.15 S3.2@10.475,27.225 ; S3.2@10.475,27.225 S3.2@10.5,27.25 ; S3.2@10.475,27.225 S3.2@10.5,27.25 ; S3.2@10.475,27.225 S3.2@10.5,27.25
  Bottom Layer w0.254: R7.1@11.2,31.8 12.2,31.8 12.5,31.5 v1(12.5,31.3) ; v1@16.109,18.391 18.6,15.9 19.825,15.9 21.525,17.6 21.525,17.621 21.831,17.621 22.011,17.8 24.5,17.8 26.87,15.43 U1.10@26.87,14.9
GPIO14: R27.1 U1.5 | length 27.8
  Bottom Layer w0.254: R27.1@11.5,13.1 11.5,13.675 11.6,13.775 12.2,13.775 13.325,14.9 15.4,14.9 15.868,14.432 15.868,12.932 17.7,11.1 18.65,11.1 19.175,10.575 20.898,10.575 21.423,11.1 30.4,11.1 33.1,13.8 33.1,14.78 U1.5@33.22,14.9
GPIO15: R29.1 U1.6 | length 28
  Bottom Layer w0.254: R29.1@10.2,13.1 10.2,13.625 10.794,14.219 11.793,14.219 11.8,14.225 11.925,14.225 13.3,15.6 15.5,15.6 16.376,14.724 16.376,13.424 18.1,11.7 18.75,11.7 19.375,11.075 20.68,11.075 21.305,11.7 30,11.7 31.95,13.65 U1.6@31.95,14.9
GPIO16: R32.2 U1.7 | length 28.2
  Bottom Layer w0.254: R32.2@8.9,13.1 8.9,13.575 9.096,13.771 9.621,13.771 10.474,14.625 11.625,14.625 13.2,16.2 15.8,16.2 16.884,15.116 16.884,13.816 18.4,12.3 18.825,12.3 19.6,11.525 20.411,11.525 21.186,12.3 29.4,12.3 30.7,13.6 30.7,14.88 U1.7@30.68,14.9
GPIO17: R34.2 U1.8 | length 28.4
  Bottom Layer w0.254: R34.2@7.6,13.1 7.6,13.65 8.128,14.178 9.452,14.178 10.313,15.038 11.313,15.038 13.05,16.775 16.125,16.775 17.392,15.508 17.392,14.108 18.6,12.9 18.85,12.9 19.625,12.125 20.293,12.125 21.068,12.9 28.9,12.9 29.41,13.41 U1.8@29.41,14.9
